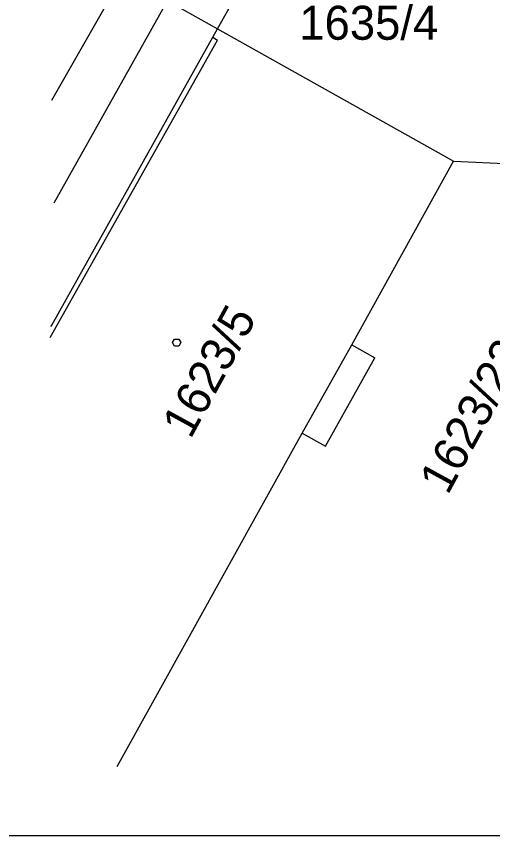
# Model space of a CAD drawing. Extents: x -762592 to -762444, y -1032635 to -1032425.
# Drawn here: x -762554.5 to -762533.47, y -1032634.69 to -1032598.54 of the extents above; entities that cross this region are included whole.
import ezdxf

# ---------------------------------------------------------------- set-up
doc = ezdxf.new("R2010")
doc.units = 0
for name, color, linetype in [('Katastr - hranice parcel', 7, 'Continuous'), ('Katastr - parcelní čísla - nedotčené ostatní', 7, 'Continuous'), ('Katastr - vnitřní kresba', 7, 'Continuous'), ('Tisk', 7, 'Continuous')]:
    doc.layers.add(name, color=color, linetype=linetype)

msp = doc.modelspace()

# ---------------------------------------------------------------- linework, layer by layer
at = {"layer": 'Katastr - hranice parcel'}
for p, q in [((-762552.926, -1032602.238), (-762543.41, -1032585.51)), ((-762545.61, -1032599.09), (-762542.1, -1032592.83)), ((-762552.83, -1032606.768), (-762547.82, -1032597.85)), ((-762547.82, -1032597.85), (-762545.61, -1032599.09)), ((-762545.82, -1032599.46), (-762545.61, -1032599.09)), ((-762545.61, -1032599.09), (-762535.64, -1032604.68)), ((-762552.583, -1032611.532), (-762545.82, -1032599.46)), ((-762535.64, -1032604.68), (-762535.19, -1032604.93)), ((-762539.69, -1032613.03), (-762535.19, -1032604.93)), ((-762535.19, -1032604.93), (-762519.17, -1032605.59)), ((-762552.932, -1032612.155), (-762552.583, -1032611.532)), ((-762552.967, -1032612.217), (-762552.932, -1032612.155)), ((-762539.69, -1032613.03), (-762538.67, -1032613.6)), ((-762540.84, -1032617.5), (-762538.67, -1032613.6)), ((-762550.045, -1032631.63), (-762541.87, -1032616.93)), ((-762541.87, -1032616.93), (-762540.84, -1032617.5))]:
    msp.add_line(p, q, dxfattribs=at)
at = {"layer": 'Katastr - parcelní čísla - nedotčené ostatní'}
msp.add_lwpolyline([(-762547.326, -1032612.783), (-762547.236, -1032612.933), (-762547.326, -1032613.083), (-762547.506, -1032613.083), (-762547.596, -1032612.933), (-762547.506, -1032612.783)], close=True, dxfattribs=at)
at = {"layer": 'Katastr - vnitřní kresba'}
for p, q in [((-762553.009, -1032612.702), (-762545.62, -1032599.58)), ((-762545.82, -1032599.46), (-762545.62, -1032599.58)), ((-762541.87, -1032616.93), (-762539.69, -1032613.03))]:
    msp.add_line(p, q, dxfattribs=at)
at = {"layer": 'Tisk'}
msp.add_lwpolyline([(-762589.528, -1032529.685), (-762592.028, -1032529.685), (-762592.028, -1032634.685), (-762443.528, -1032634.685), (-762443.528, -1032529.685), (-762446.028, -1032529.685)], dxfattribs=at)

# ---------------------------------------------------------------- texts
at = {"layer": 'Katastr - parcelní čísla - nedotčené ostatní'}
msp.add_text('1635/4', height=1.5, dxfattribs=at).set_placement((-762542.003, -1032599.568))
for s, p in [('1623/5', (-762546.809, -1032617.228)), ('1623/224', (-762535.451, -1032619.694))]:
    msp.add_text(s, height=1.5, rotation=61.3065, dxfattribs=at).set_placement(p)

doc.saveas('drawing.dxf')
